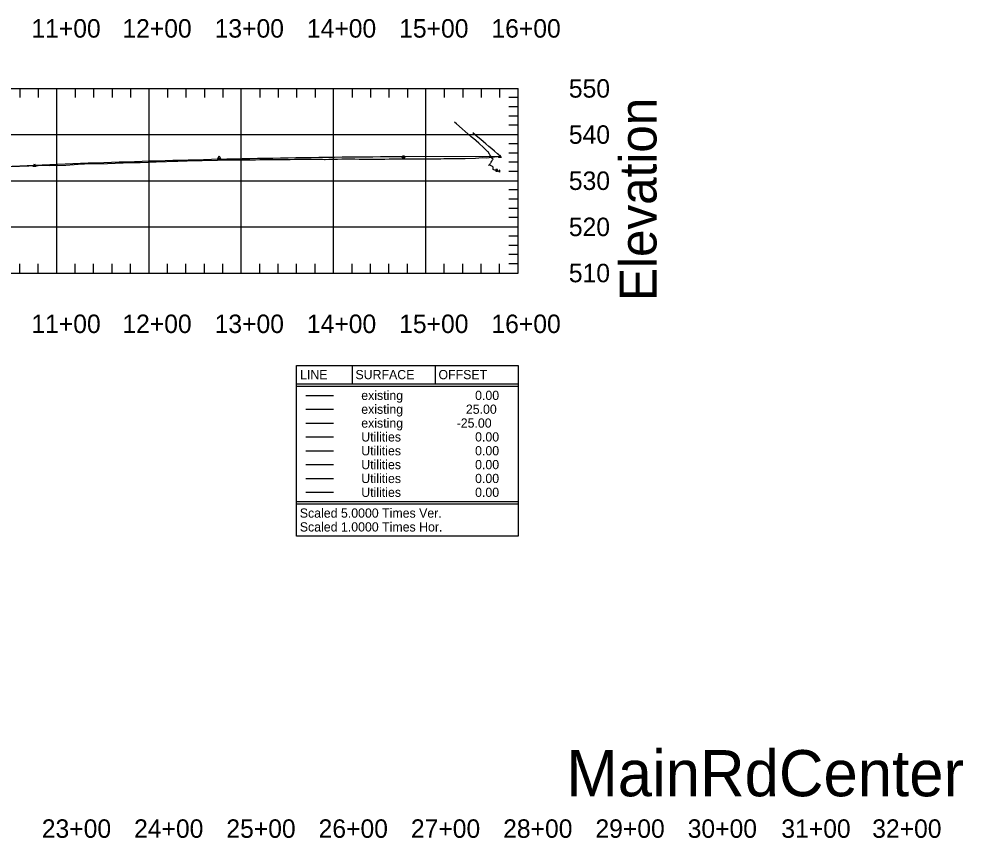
# Model space of a CAD drawing. Extents: x 704797 to 712284, y 374940 to 376945.
# Drawn here: x 709378 to 710402, y 375980 to 376868 of the extents above; entities that cross this region are included whole.
import ezdxf

# ---------------------------------------------------------------- set-up
doc = ezdxf.new("R2010")
doc.units = 0
for name, color, linetype in [('1', 7, 'Continuous'), ('10', 7, 'Continuous'), ('13', 7, 'Continuous'), ('48', 7, 'Continuous'), ('61', 7, 'Continuous'), ('63', 7, 'Continuous'), ('Default_Profile', 7, 'Continuous'), ('Existing', 7, 'Continuous')]:
    doc.layers.add(name, color=color, linetype=linetype)

msp = doc.modelspace()

# ---------------------------------------------------------------- linework, layer by layer
for points in [[(709595.4, 376719.1), (709596.9, 376716.1), (709593.9, 376716.1)], [(709795.4, 376720), (709796.9, 376717), (709793.9, 376717)], [(709899.8, 376720.5), (709901.3, 376717.5), (709898.3, 376717.5)], [(709395.4, 376710.7), (709396.9, 376707.7), (709393.9, 376707.7)]]:
    msp.add_lwpolyline(points, close=True)
at = {"layer": '10'}
msp.add_lwpolyline([(709899.8, 376703.6), (709899.5, 376703.8), (709899.5, 376702.5), (709899.4, 376701.7), (709897.5, 376703), (709896.9, 376703.5), (709895.6, 376703.6), (709895.5, 376703.6), (709895.3, 376703.6), (709895.1, 376703.6), (709894.8, 376703.7), (709894.2, 376703.9), (709893.3, 376704.1), (709892.5, 376704.3), (709892.5, 376705), (709892.4, 376705.6), (709892.3, 376706.9), (709891.6, 376707.7), (709889.5, 376708.8), (709888.8, 376709), (709888.5, 376709), (709888.3, 376709), (709887.4, 376708.8), (709887.5, 376708.9), (709887.7, 376709.1), (709888.3, 376709.6), (709888.4, 376709.8), (709889, 376710.4), (709889.2, 376710.7), (709889.7, 376711.3), (709889.9, 376711.6), (709890.4, 376712.5), (709891.1, 376713.6), (709891.8, 376715), (709892.3, 376715.8), (709891.9, 376716.4), (709889.3, 376719.7), (709889.2, 376720), (709889, 376720.3), (709888.6, 376721.1), (709886.9, 376723.6), (709886.4, 376724), (709885.6, 376724.7), (709884.5, 376725.7), (709882.2, 376727.8), (709876.9, 376733), (709871.3, 376737.9), (709870.6, 376738.5), (709868.4, 376740.3), (709862.1, 376745.5), (709858.9, 376748.5), (709852.7, 376753.9), (709850.4, 376755.8)], dxfattribs=at)
msp.add_lwpolyline([(709895.3, 376702.5), (709897.3, 376702.5), (709897.3, 376704.5), (709895.3, 376704.5)], close=True, dxfattribs=at)
at = {"layer": '13'}
msp.add_lwpolyline([(709899.8, 376719.3), (709898.6, 376720.4), (709897.2, 376721.6), (709893.9, 376724.4), (709891, 376726.7), (709887.7, 376729.5), (709884.7, 376732.1), (709881.9, 376734.4), (709879, 376736.9), (709875.9, 376739.6), (709873.8, 376741.4), (709872.9, 376742.1), (709870.3, 376744.1)], dxfattribs=at)
at = {"layer": '48'}
for p, q in [((709795.4, 376718.5), (709899.8, 376719)), ((709272, 376703.9), (709395.4, 376709.2))]:
    msp.add_line(p, q, dxfattribs=at)
msp.add_lwpolyline([(709395.4, 376709.2), (709403.7, 376709.5), (709412.1, 376709.8), (709420.4, 376710.2), (709428.7, 376710.5), (709437.1, 376710.8), (709445.4, 376711.2), (709453.7, 376711.5), (709462.1, 376711.8), (709470.4, 376712.1), (709478.7, 376712.4), (709487.1, 376712.6), (709495.4, 376712.9), (709503.7, 376713.2), (709512.1, 376713.4), (709520.4, 376713.7), (709528.7, 376714), (709537.1, 376714.2), (709545.4, 376714.4), (709553.7, 376714.7), (709562.1, 376714.9), (709570.4, 376715.1), (709578.7, 376715.3), (709587.1, 376715.5), (709603.7, 376715.9), (709612.1, 376716.1), (709620.4, 376716.3), (709628.7, 376716.5), (709637.1, 376716.6), (709645.4, 376716.8), (709653.7, 376716.9), (709662.1, 376717.1), (709670.4, 376717.2), (709678.7, 376717.3), (709687.1, 376717.5), (709695.4, 376717.6), (709703.7, 376717.7), (709712.1, 376717.8), (709720.4, 376717.9), (709728.7, 376718), (709737.1, 376718.1), (709745.4, 376718.2), (709753.7, 376718.2), (709762.1, 376718.3), (709770.4, 376718.4), (709778.7, 376718.4), (709787.1, 376718.5), (709795.4, 376718.5)], dxfattribs=at)
at = {"layer": '61'}
for p, q in [((708419.5, 376792.3), (709919.5, 376792.3)), ((709379.5, 376792.3), (709379.5, 376782.3)), ((709399.5, 376792.3), (709399.5, 376782.3)), ((709419.5, 376592.3), (709419.5, 376792.3)), ((709439.5, 376792.3), (709439.5, 376782.3)), ((709459.5, 376792.3), (709459.5, 376782.3)), ((709479.5, 376792.3), (709479.5, 376782.3)), ((709499.5, 376792.3), (709499.5, 376782.3)), ((709519.5, 376592.3), (709519.5, 376792.3)), ((709539.5, 376792.3), (709539.5, 376782.3)), ((709559.5, 376792.3), (709559.5, 376782.3)), ((709579.5, 376792.3), (709579.5, 376782.3)), ((709599.5, 376792.3), (709599.5, 376782.3)), ((709619.5, 376592.3), (709619.5, 376792.3)), ((709639.5, 376792.3), (709639.5, 376782.3)), ((709659.5, 376792.3), (709659.5, 376782.3)), ((709679.5, 376792.3), (709679.5, 376782.3)), ((709699.5, 376792.3), (709699.5, 376782.3)), ((709719.5, 376592.3), (709719.5, 376792.3)), ((709739.5, 376792.3), (709739.5, 376782.3)), ((709759.5, 376792.3), (709759.5, 376782.3)), ((709779.5, 376792.3), (709779.5, 376782.3)), ((709799.5, 376792.3), (709799.5, 376782.3)), ((709819.5, 376592.3), (709819.5, 376792.3)), ((709839.5, 376792.3), (709839.5, 376782.3)), ((709859.5, 376792.3), (709859.5, 376782.3)), ((709879.5, 376792.3), (709879.5, 376782.3)), ((709899.5, 376792.3), (709899.5, 376782.3)), ((709919.5, 376592.3), (709919.5, 376792.3)), ((709919.5, 376782.3), (709909.5, 376782.3)), ((709919.5, 376772.3), (709909.5, 376772.3)), ((709919.5, 376762.3), (709909.5, 376762.3)), ((709919.5, 376752.3), (709909.5, 376752.3)), ((708419.5, 376742.3), (709919.5, 376742.3)), ((709919.5, 376732.3), (709909.5, 376732.3)), ((709919.5, 376722.3), (709909.5, 376722.3)), ((709919.5, 376712.3), (709909.5, 376712.3)), ((709919.5, 376702.3), (709909.5, 376702.3)), ((708419.5, 376692.3), (709919.5, 376692.3)), ((709919.5, 376682.3), (709909.5, 376682.3)), ((709919.5, 376672.3), (709909.5, 376672.3)), ((709919.5, 376662.3), (709909.5, 376662.3)), ((709919.5, 376652.3), (709909.5, 376652.3)), ((708419.5, 376642.3), (709919.5, 376642.3)), ((709919.5, 376632.3), (709909.5, 376632.3)), ((709919.5, 376622.3), (709909.5, 376622.3)), ((709919.5, 376612.3), (709909.5, 376612.3)), ((709379.5, 376592.3), (709379.5, 376602.3)), ((709399.5, 376592.3), (709399.5, 376602.3)), ((709439.5, 376592.3), (709439.5, 376602.3)), ((709459.5, 376592.3), (709459.5, 376602.3)), ((709479.5, 376592.3), (709479.5, 376602.3)), ((709499.5, 376592.3), (709499.5, 376602.3)), ((709539.5, 376592.3), (709539.5, 376602.3)), ((709559.5, 376592.3), (709559.5, 376602.3)), ((709579.5, 376592.3), (709579.5, 376602.3)), ((709599.5, 376592.3), (709599.5, 376602.3)), ((709639.5, 376592.3), (709639.5, 376602.3)), ((709659.5, 376592.3), (709659.5, 376602.3)), ((709679.5, 376592.3), (709679.5, 376602.3)), ((709699.5, 376592.3), (709699.5, 376602.3)), ((709739.5, 376592.3), (709739.5, 376602.3)), ((709759.5, 376592.3), (709759.5, 376602.3)), ((709779.5, 376592.3), (709779.5, 376602.3)), ((709799.5, 376592.3), (709799.5, 376602.3)), ((709839.5, 376592.3), (709839.5, 376602.3)), ((709859.5, 376592.3), (709859.5, 376602.3)), ((709879.5, 376592.3), (709879.5, 376602.3)), ((709899.5, 376592.3), (709899.5, 376602.3)), ((709919.5, 376602.3), (709909.5, 376602.3)), ((708419.5, 376592.3), (709919.5, 376592.3)), ((709739.5, 376492.3), (709739.5, 376472.3)), ((709829.5, 376492.3), (709829.5, 376472.3)), ((709679.5, 376472.3), (709919.5, 376472.3)), ((709679.5, 376469.8), (709919.5, 376469.8)), ((709679.5, 376344.8), (709919.5, 376344.8)), ((709679.5, 376342.3), (709919.5, 376342.3))]:
    msp.add_line(p, q, dxfattribs=at)
msp.add_lwpolyline([(709679.5, 376492.3), (709919.5, 376492.3), (709919.5, 376307.3), (709679.5, 376307.3)], close=True, dxfattribs=at)
at = {"layer": '63'}
for p, q in [((709689.5, 376444.8), (709719.5, 376444.8)), ((709689.5, 376429.8), (709719.5, 376429.8))]:
    msp.add_line(p, q, dxfattribs=at)
at = {"layer": 'Default_Profile'}
for p, q in [((709689.5, 376414.8), (709719.5, 376414.8)), ((709689.5, 376399.8), (709719.5, 376399.8)), ((709689.5, 376384.8), (709719.5, 376384.8)), ((709689.5, 376369.8), (709719.5, 376369.8)), ((709689.5, 376354.8), (709719.5, 376354.8))]:
    msp.add_line(p, q, dxfattribs=at)
at = {"layer": 'Existing'}
msp.add_line((709689.5, 376459.8), (709719.5, 376459.8), dxfattribs=at)
msp.add_lwpolyline([(709369.1, 376707.8), (709399.2, 376708.9), (709400.6, 376709), (709411.2, 376708.8), (709429.3, 376709.3), (709447.5, 376710.6), (709449.7, 376710.7), (709474.6, 376710.9), (709499.8, 376712.2), (709510, 376712), (709527.4, 376712.8), (709550.1, 376713.6), (709550.6, 376713.6), (709560.8, 376713.9), (709593.6, 376714.7), (709594.8, 376714.8), (709602.3, 376714.8), (709606.9, 376714.8), (709611.6, 376714.8), (709614.5, 376714.8), (709616.3, 376714.8), (709621, 376714.9), (709625.6, 376715), (709630.3, 376715), (709632.9, 376715.1), (709635, 376715.1), (709639.7, 376715.2), (709643.9, 376715.4), (709644.3, 376715.4), (709645.7, 376715.4), (709649, 376715.4), (709653.7, 376715.4), (709658.3, 376715.4), (709663, 376715.4), (709667.7, 376715.4), (709671.7, 376715.4), (709672.4, 376715.4), (709677, 376715.5), (709681.7, 376715.5), (709686.4, 376715.6), (709688.4, 376715.6), (709691.1, 376715.6), (709691.3, 376715.6), (709695.7, 376715.6), (709700.4, 376715.5), (709705.1, 376715.5), (709707.6, 376715.5), (709709.8, 376715.4), (709710.5, 376715.4), (709714.4, 376715.5), (709719.1, 376715.7), (709723.8, 376715.8), (709728.4, 376715.9), (709733.1, 376716), (709733.6, 376716), (709737.1, 376716.1), (709737.8, 376716.1), (709742.5, 376715.9), (709747.1, 376715.8), (709747.9, 376715.8), (709751.8, 376715.8), (709756.5, 376715.8), (709761.2, 376715.8), (709765.8, 376715.8), (709770.5, 376715.8), (709775, 376715.8), (709775.2, 376715.8), (709779.8, 376715.9), (709780.2, 376715.9), (709784.5, 376715.9), (709789.2, 376716), (709790.5, 376716), (709793.9, 376715.9), (709798.5, 376715.9), (709802.6, 376715.9), (709803.2, 376715.9), (709807.9, 376715.9), (709812.6, 376715.9), (709817.2, 376715.9), (709820.4, 376716), (709821.9, 376716), (709822.6, 376716), (709826.6, 376716), (709831.2, 376716.1), (709835.9, 376716.1), (709839, 376716.2), (709840.6, 376716.2), (709845.3, 376716.2), (709849.9, 376716.3), (709862.1, 376716.4), (709873.5, 376716.7), (709876.9, 376717.2), (709881, 376717.5), (709885.1, 376717), (709899.8, 376719)], dxfattribs=at)

# ---------------------------------------------------------------- texts
at = {"layer": '1'}
for s, height, p in [(' LINE ', 10, (709679.5, 376477.3)), (' SURFACE ', 10, (709739.5, 376477.3)), (' OFFSET ', 10, (709829.5, 376477.3)), ('existing', 10, (709749.5, 376454.8)), ('0.00', 10, (709872.9, 376454.8)), ('existing', 10, (709749.5, 376439.8)), ('25.00', 10, (709862.9, 376439.8)), ('existing', 10, (709749.5, 376424.8)), ('-25.00', 10, (709852.9, 376424.8)), ('Utilities', 10, (709749.5, 376409.8)), ('0.00', 10, (709872.9, 376409.8)), ('Utilities', 10, (709749.5, 376394.8)), ('0.00', 10, (709872.9, 376394.8)), ('Utilities', 10, (709749.5, 376379.8)), ('0.00', 10, (709872.9, 376379.8)), ('Utilities', 10, (709749.5, 376364.8)), ('0.00', 10, (709872.9, 376364.8)), ('Utilities', 10, (709749.5, 376349.8)), ('0.00', 10, (709872.9, 376349.8)), ('Scaled 5.0000 Times Ver.', 10, (709682.9, 376327.3)), ('Scaled 1.0000 Times Hor.', 10, (709682.9, 376312.3)), ('MainRdCenter', 50, (709971.8, 376025.5))]:
    msp.add_text(s, height=height, dxfattribs=at).set_placement(p)
at = {"layer": '61'}
for s, p in [('11+00', (709392, 376847.3)), ('12+00', (709490.6, 376847.3)), ('13+00', (709590.6, 376847.3)), ('14+00', (709690.6, 376847.3)), ('15+00', (709790.6, 376847.3)), ('16+00', (709890.6, 376847.3)), ('550', (709974.5, 376782.3)), ('550', (709974.5, 376782.3)), ('540', (709974.5, 376732.3)), ('530', (709974.5, 376682.3)), ('520', (709974.5, 376632.3)), ('510', (709974.5, 376582.3)), ('11+00', (709392, 376527.3)), ('12+00', (709490.6, 376527.3)), ('13+00', (709590.6, 376527.3)), ('14+00', (709690.6, 376527.3)), ('15+00', (709790.6, 376527.3)), ('16+00', (709890.6, 376527.3)), ('23+00', (709403.3, 375980.5)), ('24+00', (709503.3, 375980.5)), ('25+00', (709603.3, 375980.5)), ('26+00', (709703.3, 375980.5)), ('27+00', (709803.3, 375980.5)), ('28+00', (709903.3, 375980.5)), ('29+00', (710003.3, 375980.5)), ('30+00', (710103.3, 375980.5)), ('31+00', (710204.8, 375980.5)), ('32+00', (710303.3, 375980.5))]:
    msp.add_text(s, height=20, dxfattribs=at).set_placement(p)
msp.add_text('Elevation', height=40, rotation=90, dxfattribs=at).set_placement((710069.5, 376562.1))

doc.saveas('drawing.dxf')
